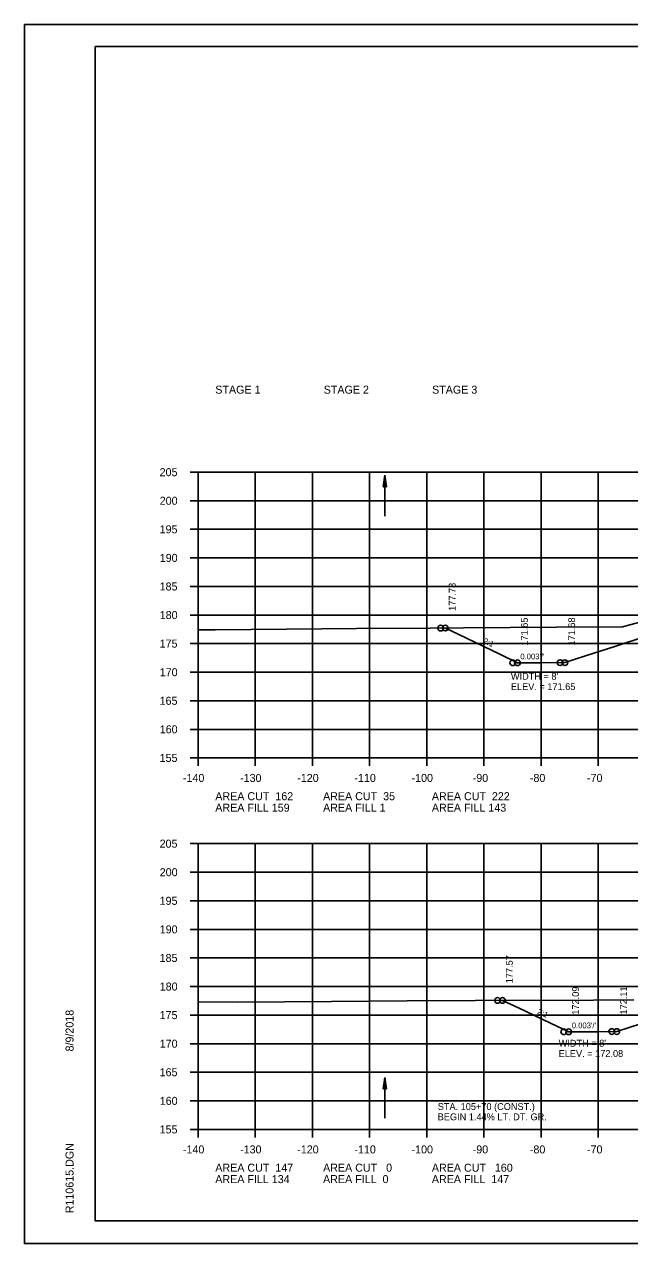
# Model space of a CAD drawing. Extents: x 1372132 to 1372465, y 380083 to 381790.
# Drawn here: x 1372131.6 to 1372237.5, y 380510.2 to 380723.5 of the extents above; entities that cross this region are included whole.
import ezdxf

# ---------------------------------------------------------------- set-up
doc = ezdxf.new("R2010")
doc.units = 0
for name, color, linetype in [('R_Axis', 7, 'Continuous'), ('R_Axis Annot', 7, 'Continuous'), ('R_Border', 7, 'Continuous'), ('R_Dimension', 7, 'Continuous'), ('R_Draft', 7, 'Continuous'), ('R_Exist Surface', 7, 'Continuous'), ('R_Fin Surface', 7, 'Continuous'), ('R_Grid', 7, 'Continuous'), ('R_No Plot', 7, 'Continuous'), ('R_Xsect Elev', 7, 'Continuous'), ('R_Xsect Slope', 7, 'Continuous')]:
    doc.layers.add(name, color=color, linetype=linetype)

msp = doc.modelspace()

# ---------------------------------------------------------------- linework, layer by layer
at = {"layer": 'R_Axis'}
for p, q in [((1372160.61, 380645.15), (1372162.01, 380645.15)), ((1372162.01, 380595.15), (1372162.01, 380645.15)), ((1372160.61, 380640.15), (1372162.01, 380640.15)), ((1372160.61, 380635.15), (1372162.01, 380635.15)), ((1372160.61, 380630.15), (1372162.01, 380630.15)), ((1372160.61, 380625.15), (1372162.01, 380625.15)), ((1372160.61, 380620.15), (1372162.01, 380620.15)), ((1372160.61, 380615.15), (1372162.01, 380615.15)), ((1372160.61, 380610.15), (1372162.01, 380610.15)), ((1372160.61, 380605.15), (1372162.01, 380605.15)), ((1372160.61, 380600.15), (1372162.01, 380600.15)), ((1372160.61, 380595.15), (1372162.01, 380595.15)), ((1372162.01, 380595.15), (1372442.01, 380595.15)), ((1372162.01, 380593.75), (1372162.01, 380595.15)), ((1372172.01, 380593.75), (1372172.01, 380595.15)), ((1372182.01, 380593.75), (1372182.01, 380595.15)), ((1372192.01, 380593.75), (1372192.01, 380595.15)), ((1372202.01, 380593.75), (1372202.01, 380595.15)), ((1372212.01, 380593.75), (1372212.01, 380595.15)), ((1372222.01, 380593.75), (1372222.01, 380595.15)), ((1372232.01, 380593.75), (1372232.01, 380595.15)), ((1372160.61, 380580.15), (1372162.01, 380580.15)), ((1372162.01, 380530.15), (1372162.01, 380580.15)), ((1372160.61, 380575.15), (1372162.01, 380575.15)), ((1372160.61, 380570.15), (1372162.01, 380570.15)), ((1372160.61, 380565.15), (1372162.01, 380565.15)), ((1372160.61, 380560.15), (1372162.01, 380560.15)), ((1372160.61, 380555.15), (1372162.01, 380555.15)), ((1372160.61, 380550.15), (1372162.01, 380550.15)), ((1372160.61, 380545.15), (1372162.01, 380545.15)), ((1372160.61, 380540.15), (1372162.01, 380540.15)), ((1372160.61, 380535.15), (1372162.01, 380535.15)), ((1372160.61, 380530.15), (1372162.01, 380530.15)), ((1372162.01, 380530.15), (1372442.01, 380530.15)), ((1372162.01, 380528.75), (1372162.01, 380530.15)), ((1372172.01, 380528.75), (1372172.01, 380530.15)), ((1372182.01, 380528.75), (1372182.01, 380530.15)), ((1372192.01, 380528.75), (1372192.01, 380530.15)), ((1372202.01, 380528.75), (1372202.01, 380530.15)), ((1372212.01, 380528.75), (1372212.01, 380530.15)), ((1372222.01, 380528.75), (1372222.01, 380530.15)), ((1372232.01, 380528.75), (1372232.01, 380530.15))]:
    msp.add_line(p, q, dxfattribs=at)
at = {"layer": 'R_Border'}
for p, q in [((1372144.01, 380719.61), (1372460.19, 380719.61)), ((1372144.01, 380514.15), (1372144.01, 380719.61)), ((1372144.01, 380514.15), (1372144.01, 380514.15)), ((1372460.19, 380514.15), (1372144.01, 380514.15))]:
    msp.add_line(p, q, dxfattribs=at)
at = {"layer": 'R_Dimension'}
for p, q in [((1372194.39, 380642.6), (1372194.69, 380644.6)), ((1372194.39, 380642.6), (1372194.69, 380644.6)), ((1372194.44, 380642.6), (1372194.69, 380644.26)), ((1372194.44, 380642.6), (1372194.69, 380644.26)), ((1372194.49, 380642.6), (1372194.69, 380643.92)), ((1372194.49, 380642.6), (1372194.69, 380643.92)), ((1372194.54, 380642.6), (1372194.69, 380643.59)), ((1372194.54, 380642.6), (1372194.69, 380643.59)), ((1372194.99, 380642.6), (1372194.69, 380644.6)), ((1372194.99, 380642.6), (1372194.69, 380644.6)), ((1372194.94, 380642.6), (1372194.69, 380644.26)), ((1372194.94, 380642.6), (1372194.69, 380644.26)), ((1372194.88, 380642.6), (1372194.69, 380643.92)), ((1372194.88, 380642.6), (1372194.69, 380643.92)), ((1372194.83, 380642.6), (1372194.69, 380643.59)), ((1372194.83, 380642.6), (1372194.69, 380643.59)), ((1372194.39, 380642.6), (1372194.99, 380642.6)), ((1372194.39, 380642.6), (1372194.99, 380642.6)), ((1372194.59, 380642.6), (1372194.69, 380643.25)), ((1372194.59, 380642.6), (1372194.69, 380643.25)), ((1372194.64, 380642.6), (1372194.69, 380642.91)), ((1372194.64, 380642.6), (1372194.69, 380642.91)), ((1372194.78, 380642.6), (1372194.69, 380643.25)), ((1372194.78, 380642.6), (1372194.69, 380643.25)), ((1372194.73, 380642.6), (1372194.69, 380642.91)), ((1372194.73, 380642.6), (1372194.69, 380642.91)), ((1372194.39, 380537.23), (1372194.69, 380539.23)), ((1372194.39, 380537.23), (1372194.69, 380539.23)), ((1372194.44, 380537.23), (1372194.69, 380538.9)), ((1372194.44, 380537.23), (1372194.69, 380538.9)), ((1372194.99, 380537.23), (1372194.69, 380539.23)), ((1372194.99, 380537.23), (1372194.69, 380539.23)), ((1372194.94, 380537.23), (1372194.69, 380538.9)), ((1372194.94, 380537.23), (1372194.69, 380538.9)), ((1372194.39, 380537.23), (1372194.99, 380537.23)), ((1372194.39, 380537.23), (1372194.99, 380537.23)), ((1372194.49, 380537.23), (1372194.69, 380538.55)), ((1372194.49, 380537.23), (1372194.69, 380538.55)), ((1372194.54, 380537.23), (1372194.69, 380538.22)), ((1372194.54, 380537.23), (1372194.69, 380538.22)), ((1372194.59, 380537.23), (1372194.69, 380537.88)), ((1372194.59, 380537.23), (1372194.69, 380537.88)), ((1372194.64, 380537.23), (1372194.69, 380537.55)), ((1372194.64, 380537.23), (1372194.69, 380537.55)), ((1372194.88, 380537.23), (1372194.69, 380538.55)), ((1372194.88, 380537.23), (1372194.69, 380538.55)), ((1372194.83, 380537.23), (1372194.69, 380538.22)), ((1372194.83, 380537.23), (1372194.69, 380538.22)), ((1372194.78, 380537.23), (1372194.69, 380537.88)), ((1372194.78, 380537.23), (1372194.69, 380537.88)), ((1372194.73, 380537.23), (1372194.69, 380537.55)), ((1372194.73, 380537.23), (1372194.69, 380537.55))]:
    msp.add_line(p, q, dxfattribs=at)
at = {"layer": 'R_Draft'}
for p, q in [((1372194.69, 380637.46), (1372194.69, 380644.6)), ((1372194.69, 380532.09), (1372194.69, 380539.23))]:
    msp.add_line(p, q, dxfattribs=at)
at = {"layer": 'R_Exist Surface'}
for points in [[(1372162.01, 380617.59), (1372165, 380617.57), (1372171.23, 380617.63), (1372183.72, 380617.71), (1372189.74, 380617.77), (1372202.61, 380617.85), (1372208.42, 380617.91), (1372224.73, 380618.03), (1372236.31, 380618.08), (1372237.31, 380618.36), (1372242.52, 380619.74)], [(1372162.01, 380552.48), (1372168.88, 380552.44), (1372185.37, 380552.55), (1372198.56, 380552.63), (1372210.55, 380552.71), (1372231.2, 380552.76), (1372238.23, 380552.8)]]:
    msp.add_lwpolyline(points, dxfattribs=at)
at = {"layer": 'R_Fin Surface'}
for points in [[(1372205.26, 380617.88), (1372206.28, 380617.39), (1372207.65, 380616.73), (1372214.79, 380613.29), (1372217.89, 380611.8), (1372221.94, 380611.81), (1372226.17, 380611.82), (1372229.79, 380613), (1372234.91, 380614.67), (1372240.37, 380616.44)], [(1372215.26, 380552.72), (1372218.17, 380551.34), (1372223.64, 380548.75), (1372225.77, 380547.74), (1372226.84, 380547.23), (1372232.05, 380547.25), (1372235.25, 380547.26), (1372239.6, 380548.66)]]:
    msp.add_lwpolyline(points, dxfattribs=at)
at = {"layer": 'R_Grid'}
for p, q in [((1372162.01, 380645.15), (1372442.01, 380645.15)), ((1372162.01, 380595.15), (1372162.01, 380645.15)), ((1372172.01, 380595.15), (1372172.01, 380645.15)), ((1372182.01, 380595.15), (1372182.01, 380645.15)), ((1372192.01, 380595.15), (1372192.01, 380645.15)), ((1372202.01, 380595.15), (1372202.01, 380645.15)), ((1372212.01, 380595.15), (1372212.01, 380645.15)), ((1372222.01, 380595.15), (1372222.01, 380645.15)), ((1372232.01, 380595.15), (1372232.01, 380645.15)), ((1372162.01, 380640.15), (1372442.01, 380640.15)), ((1372162.01, 380635.15), (1372442.01, 380635.15)), ((1372162.01, 380630.15), (1372442.01, 380630.15)), ((1372162.01, 380625.15), (1372442.01, 380625.15)), ((1372162.01, 380620.15), (1372442.01, 380620.15)), ((1372162.01, 380615.15), (1372442.01, 380615.15)), ((1372162.01, 380610.15), (1372442.01, 380610.15)), ((1372162.01, 380605.15), (1372442.01, 380605.15)), ((1372162.01, 380600.15), (1372442.01, 380600.15)), ((1372162.01, 380595.15), (1372442.01, 380595.15)), ((1372162.01, 380580.15), (1372442.01, 380580.15)), ((1372162.01, 380530.15), (1372162.01, 380580.15)), ((1372172.01, 380530.15), (1372172.01, 380580.15)), ((1372182.01, 380530.15), (1372182.01, 380580.15)), ((1372192.01, 380530.15), (1372192.01, 380580.15)), ((1372202.01, 380530.15), (1372202.01, 380580.15)), ((1372212.01, 380530.15), (1372212.01, 380580.15)), ((1372222.01, 380530.15), (1372222.01, 380580.15)), ((1372232.01, 380530.15), (1372232.01, 380580.15)), ((1372162.01, 380575.15), (1372442.01, 380575.15)), ((1372162.01, 380570.15), (1372442.01, 380570.15)), ((1372162.01, 380565.15), (1372442.01, 380565.15)), ((1372162.01, 380560.15), (1372442.01, 380560.15)), ((1372162.01, 380555.15), (1372442.01, 380555.15)), ((1372162.01, 380550.15), (1372442.01, 380550.15)), ((1372162.01, 380545.15), (1372442.01, 380545.15)), ((1372162.01, 380540.15), (1372442.01, 380540.15)), ((1372162.01, 380535.15), (1372442.01, 380535.15)), ((1372162.01, 380530.15), (1372442.01, 380530.15))]:
    msp.add_line(p, q, dxfattribs=at)
at = {"layer": 'R_No Plot'}
for p, q in [((1372131.61, 380723.5), (1372464.95, 380723.5)), ((1372131.61, 380510.17), (1372464.95, 380510.17))]:
    msp.add_line(p, q, dxfattribs=at)
for points in [[(1372131.61, 380723.5), (1372464.95, 380723.5), (1372464.95, 380510.17), (1372131.61, 380510.17)], [(1372377.93, 380719.61), (1372377.93, 380709.73), (1372413.67, 380709.73), (1372413.67, 380706.81), (1372436.87, 380706.81), (1372436.87, 380682.48), (1372460.19, 380682.48), (1372460.19, 380514.15), (1372144.01, 380514.15), (1372144.01, 380719.61)]]:
    msp.add_lwpolyline(points, close=True, dxfattribs=at)
for centre in [(1372204.44, 380617.87), (1372205.26, 380617.88), (1372217.06, 380611.8), (1372217.89, 380611.8), (1372225.33, 380611.82), (1372226.17, 380611.82), (1372214.41, 380552.72), (1372215.26, 380552.72), (1372225.98, 380547.23), (1372226.84, 380547.23), (1372234.39, 380547.26), (1372235.25, 380547.26)]:
    msp.add_circle(centre, 0.5, dxfattribs=at)

# ---------------------------------------------------------------- texts
at = {"layer": 'R_Axis Annot'}
for s, p in [('STAGE 1', (1372165.01, 380658.89)), ('STAGE 2', (1372183.98, 380658.89)), ('STAGE 3', (1372202.94, 380658.89)), ('205', (1372155.27, 380644.45)), ('200', (1372155.29, 380639.45)), ('195', (1372155.27, 380634.45)), ('190', (1372155.29, 380629.45)), ('185', (1372155.27, 380624.45)), ('180', (1372155.29, 380619.45)), ('175', (1372155.27, 380614.45)), ('170', (1372155.29, 380609.45)), ('165', (1372155.27, 380604.45)), ('160', (1372155.29, 380599.45)), ('155', (1372155.27, 380594.45)), ('-140', (1372159.35, 380590.95)), ('-130', (1372169.35, 380590.95)), ('-120', (1372179.35, 380590.95)), ('-110', (1372189.35, 380590.95)), ('-100', (1372199.35, 380590.95)), ('-90', (1372210.05, 380590.95)), ('-80', (1372220.05, 380590.95)), ('-70', (1372230.05, 380590.95)), ('AREA CUT  162', (1372165.01, 380587.75)), ('AREA CUT  35', (1372183.87, 380587.75)), ('AREA CUT  222', (1372202.9, 380587.75)), ('AREA FILL 159', (1372165.01, 380585.75)), ('AREA FILL 1', (1372183.87, 380585.75)), ('AREA FILL 143', (1372202.9, 380585.75)), ('205', (1372155.27, 380579.45)), ('200', (1372155.29, 380574.45)), ('195', (1372155.27, 380569.45)), ('190', (1372155.29, 380564.45)), ('185', (1372155.27, 380559.45)), ('180', (1372155.29, 380554.45)), ('175', (1372155.27, 380549.45)), ('170', (1372155.29, 380544.45)), ('165', (1372155.27, 380539.45)), ('160', (1372155.29, 380534.45)), ('155', (1372155.27, 380529.45)), ('-140', (1372159.35, 380525.95)), ('-130', (1372169.35, 380525.95)), ('-120', (1372179.35, 380525.95)), ('-110', (1372189.35, 380525.95)), ('-100', (1372199.35, 380525.95)), ('-90', (1372210.05, 380525.95)), ('-80', (1372220.05, 380525.95)), ('-70', (1372230.05, 380525.95)), ('AREA CUT  147', (1372165.01, 380522.75)), ('AREA CUT   0', (1372183.87, 380522.75)), ('AREA CUT   160', (1372202.9, 380522.75)), ('AREA FILL 134', (1372165.01, 380520.75)), ('AREA FILL  0', (1372183.87, 380520.75)), ('AREA FILL  147', (1372202.9, 380520.75))]:
    msp.add_text(s, height=1.4, dxfattribs=at).set_placement(p)
at = {"layer": 'R_Border'}
for s, p in [('8/9/2018', (1372140.21, 380543.79)), ('R110615.DGN', (1372140.21, 380515.47))]:
    msp.add_text(s, height=1.4, rotation=90, dxfattribs=at).set_placement(p)
at = {"layer": 'R_Dimension'}
for s, p in [("WIDTH = 8'", (1372216.73, 380608.83)), ('ELEV. = 171.65', (1372216.73, 380607.03)), ("WIDTH = 8'", (1372225.09, 380544.63)), ('ELEV. = 172.08', (1372225.09, 380542.83))]:
    msp.add_text(s, height=1.2, dxfattribs=at).set_placement(p)
at = {"layer": 'R_Draft'}
for s, p in [('STA. 105+70 (CONST.)', (1372203.93, 380533.55)), ('BEGIN 1.44% LT. DT. GR.', (1372203.93, 380531.75))]:
    msp.add_text(s, height=1.2, dxfattribs=at).set_placement(p)
at = {"layer": 'R_Xsect Elev'}
for s, p in [('177.73', (1372207.06, 380620.88)), ('171.65', (1372219.69, 380614.8)), ('171.68', (1372227.97, 380614.82)), ('177.57', (1372217.06, 380555.72)), ('172.09', (1372228.64, 380550.23)), ('172.11', (1372237.05, 380550.26))]:
    msp.add_text(s, height=1.2, rotation=90, dxfattribs=at).set_placement(p)
at = {"layer": 'R_Xsect Slope'}
for s, rotation, p in [('2:1', 334.3055, (1372211.79, 380615.29)), ("0.003'/'", 0.1579, (1372218.38, 380612.4)), ('2:1', 334.6572, (1372221.27, 380550.43)), ("0.003'/'", 0.1982, (1372227.39, 380547.84))]:
    msp.add_text(s, height=1, rotation=rotation, dxfattribs=at).set_placement(p)

doc.saveas('drawing.dxf')
